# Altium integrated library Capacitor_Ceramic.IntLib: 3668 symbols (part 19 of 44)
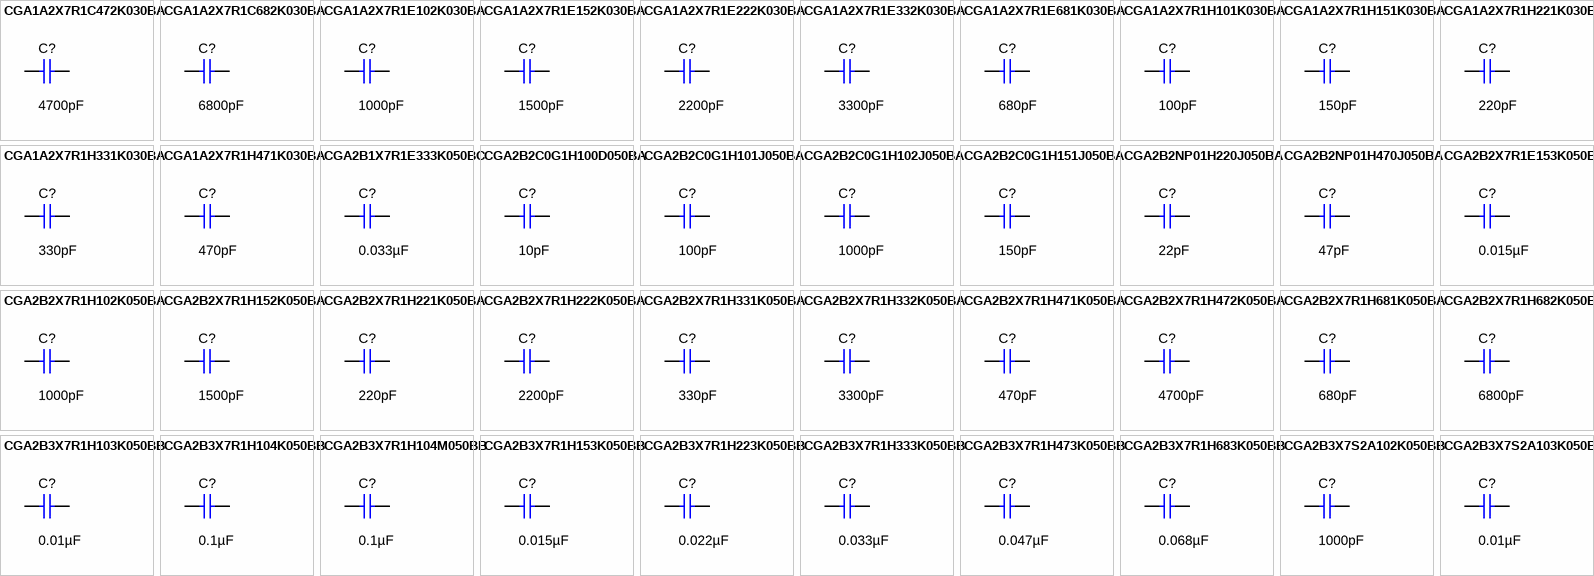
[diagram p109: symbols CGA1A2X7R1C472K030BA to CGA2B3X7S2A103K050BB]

## CGA2B2C0G1H101J050BA
designator C?  ValueDisplayed: 100pF  (hidden comment: CGA2B2C0G1H101J050BA)
CAP, CERM, 100 pF, 50 V,+/- 5%, C0G/NP0, AEC-Q200 Grade 1, 0402; Manufacturer: TDK; Polarized: N; CompType: Capacitor; Value: 100pF; U/M: EA; Cap_F: 0.0000000001; Tolerance_%: 5; VDC_V: 50; Value2: 50V; TaMin_C: -55; TaMax_C: 125; Cap_Case: 0402; SizeArea_mm2: 0.5; SizeAreaWB_mm2: 3; SizeX_mm: 1; SizeZ_mm: 0.6; AEC Category: Q200; AEC Qualified: Y; Green_Lifecycle: Active; Green_REACh: Passed
signal-integrity model Cap
simulation model Cap
footprint 0402
footprint 0402M
footprint 0402L
footprint 0402S
pins: 1, 2

## CGA2B2C0G1H102J050BA
designator C?  ValueDisplayed: 1000pF  (hidden comment: CGA2B2C0G1H102J050BA)
CAP, CERM, 1000 pF, 50 V,+/- 5%, C0G/NP0, AEC-Q200 Grade 1, 0402; Manufacturer: TDK; Polarized: N; CompType: Capacitor; Value: 1000pF; U/M: EA; Cap_F: 0.000000001; Tolerance_%: 5; VDC_V: 50; Value2: 50V; TaMin_C: -55; TaMax_C: 125; Cap_Case: 0402; SizeArea_mm2: 0.5; SizeAreaWB_mm2: 3; SizeX_mm: 1; SizeZ_mm: 0.6; AEC Category: Q200; AEC Qualified: Y; Green_Lifecycle: Active; Green_REACh: Passed
signal-integrity model Cap
simulation model Cap
footprint 0402
footprint 0402M
footprint 0402L
footprint 0402S
pins: 1, 2

## CGA2B2C0G1H151J050BA
designator C?  ValueDisplayed: 150pF  (hidden comment: CGA2B2C0G1H151J050BA)
CAP, CERM, 150 pF, 50 V,+/- 5%, C0G/NP0, AEC-Q200 Grade 1, 0402; Manufacturer: TDK; Polarized: N; CompType: Capacitor; Value: 150pF; U/M: EA; Cap_F: 0.00000000015; Tolerance_%: 5; VDC_V: 50; Value2: 50V; TaMin_C: -55; TaMax_C: 125; Cap_Case: 0402; SizeArea_mm2: 0.5; SizeAreaWB_mm2: 3; SizeX_mm: 1; SizeZ_mm: 0.6; AEC Category: Q200; AEC Qualified: Y
signal-integrity model Cap
simulation model Cap
footprint 0402
footprint 0402M
footprint 0402L
footprint 0402S
pins: 1, 2

## CGA2B2NP01H220J050BA
designator C?  ValueDisplayed: 22pF  (hidden comment: CGA2B2NP01H220J050BA)
CAP, CERM, 22 pF, 50 V,+/- 5%, C0G/NP0, AEC-Q200 Grade 1, 0402; Manufacturer: TDK; Polarized: N; CompType: Capacitor; Value: 22pF; U/M: EA; Cap_F: 0.000000000022; Tolerance_%: 5; VDC_V: 50; Value2: 50V; TaMin_C: -55; TaMax_C: 125; Cap_Case: 0402; SizeArea_mm2: 0.5; SizeAreaWB_mm2: 3; SizeX_mm: 1; SizeZ_mm: 0.6; AEC Category: Q200; AEC Qualified: Y
signal-integrity model Cap
simulation model Cap
footprint 0402
footprint 0402M
footprint 0402L
footprint 0402S
pins: 1, 2

## CGA2B2NP01H470J050BA
designator C?  ValueDisplayed: 47pF  (hidden comment: CGA2B2NP01H470J050BA)
CAP, CERM, 47 pF, 50 V,+/- 5%, C0G/NP0, AEC-Q200 Grade 0, 0402; Manufacturer: TDK; Polarized: N; CompType: Capacitor; Value: 47pF; U/M: EA; Cap_F: 0.000000000047; Tolerance_%: 5; VDC_V: 50; Value2: 50V; TaMin_C: -55; TaMax_C: 150; Cap_Case: 0402; SizeArea_mm2: 0.5; SizeAreaWB_mm2: 3; SizeX_mm: 1; SizeZ_mm: 0.6; AEC Category: Q200; AEC Qualified: Y; AEC Grade: 0
signal-integrity model Cap
simulation model Cap
footprint 0402
footprint 0402M
footprint 0402L
footprint 0402S
pins: 1, 2

## CGA2B2X7R1E153K050BA
designator C?  ValueDisplayed: 0.015µF  (hidden comment: CGA2B2X7R1E153K050BA)
CAP, CERM, 0.015 µF, 25 V,+/- 10%, X7R, AEC-Q200 Grade 1, 0402; Manufacturer: TDK; Polarized: N; CompType: Capacitor; Value: 0.015uF; U/M: EA; Cap_F: 0.000000015; Tolerance_%: 10; VDC_V: 25; Value2: 25V; TaMin_C: -55; TaMax_C: 125; Cap_Case: 0402; SizeArea_mm2: 0.5; SizeAreaWB_mm2: 3; SizeX_mm: 1; SizeZ_mm: 0.6; AEC Category: Q200; AEC Qualified: Y
signal-integrity model Cap
simulation model Cap
footprint 0402
footprint 0402M
footprint 0402L
footprint 0402S
pins: 1, 2

## CGA2B2X7R1H102K050BA
designator C?  ValueDisplayed: 1000pF  (hidden comment: CGA2B2X7R1H102K050BA)
CAP, CERM, 1000 pF, 50 V,+/- 10%, X7R, AEC-Q200 Grade 1, 0402; Manufacturer: TDK; Polarized: N; CompType: Capacitor; Value: 1000pF; U/M: EA; Cap_F: 0.000000001; Tolerance_%: 10; ESR_ohm: 2.25564; Value1: 2.25564 ohm; VDC_V: 50; Value2: 50V; IRMS_A: 0.280466; TaMin_C: -55; TaMax_C: 125; Cap_Case: 0402; SizeArea_mm2: 0.5; SizeAreaWB_mm2: 3; SizeX_mm: 1; SizeZ_mm: 0.6; AEC Category: Q200; AEC Qualified: Y
signal-integrity model Cap
simulation model Cap
footprint 0402
footprint 0402M
footprint 0402L
footprint 0402S
pins: 1, 2

## CGA2B2X7R1H152K050BA
designator C?  ValueDisplayed: 1500pF  (hidden comment: CGA2B2X7R1H152K050BA)
CAP, CERM, 1500 pF, 50 V,+/- 10%, X7R, AEC-Q200 Grade 1, 0402; Manufacturer: TDK; Polarized: N; CompType: Capacitor; Value: 1500pF; U/M: EA; Cap_F: 0.0000000015; Tolerance_%: 10; ESR_ohm: 1.65812; Value1: 1.65812 ohm; VDC_V: 50; Value2: 50V; IRMS_A: 0.254831; TaMin_C: -55; TaMax_C: 125; Cap_Case: 0402; SizeArea_mm2: 0.5; SizeAreaWB_mm2: 3; SizeX_mm: 1; SizeZ_mm: 0.6; AEC Category: Q200; AEC Qualified: Y
signal-integrity model Cap
simulation model Cap
footprint 0402
footprint 0402M
footprint 0402L
footprint 0402S
pins: 1, 2

## CGA2B2X7R1H221K050BA
designator C?  ValueDisplayed: 220pF  (hidden comment: CGA2B2X7R1H221K050BA)
CAP, CERM, 220 pF, 50 V,+/- 10%, X7R, AEC-Q200 Grade 1, 0402; Manufacturer: TDK; Polarized: N; CompType: Capacitor; Value: 220pF; U/M: EA; Cap_F: 0.00000000022; Tolerance_%: 10; ESR_ohm: 9.829; Value1: 9.829 ohm; VDC_V: 50; Value2: 50V; IRMS_A: 0.201345; TaMin_C: -55; TaMax_C: 125; Cap_Case: 0402; SizeArea_mm2: 0.5; SizeAreaWB_mm2: 3; SizeX_mm: 1; SizeZ_mm: 0.6; AEC Category: Q200; AEC Qualified: Y
signal-integrity model Cap
simulation model Cap
footprint 0402
footprint 0402M
footprint 0402L
footprint 0402S
pins: 1, 2

## CGA2B2X7R1H222K050BA
designator C?  ValueDisplayed: 2200pF  (hidden comment: CGA2B2X7R1H222K050BA)
CAP, CERM, 2200 pF, 50 V,+/- 10%, X7R, AEC-Q200 Grade 1, 0402; Manufacturer: TDK; Polarized: N; CompType: Capacitor; Value: 2200pF; U/M: EA; Cap_F: 0.0000000022; Tolerance_%: 10; ESR_ohm: 1.07794; Value1: 1.07794 ohm; VDC_V: 50; Value2: 50V; IRMS_A: 0.264071; TaMin_C: -55; TaMax_C: 125; Cap_Case: 0402; SizeArea_mm2: 0.5; SizeAreaWB_mm2: 3; SizeX_mm: 1; SizeZ_mm: 0.6; AEC Category: Q200; AEC Qualified: Y
signal-integrity model Cap
simulation model Cap
footprint 0402
footprint 0402M
footprint 0402L
footprint 0402S
pins: 1, 2

## CGA2B2X7R1H331K050BA
designator C?  ValueDisplayed: 330pF  (hidden comment: CGA2B2X7R1H331K050BA)
CAP, CERM, 330 pF, 50 V,+/- 10%, X7R, AEC-Q200 Grade 1, 0402; Manufacturer: TDK; Polarized: N; CompType: Capacitor; Value: 330pF; U/M: EA; Cap_F: 0.00000000033; Tolerance_%: 10; ESR_ohm: 6.53276; Value1: 6.53276 ohm; VDC_V: 50; Value2: 50V; IRMS_A: 0.212649; TaMin_C: -55; TaMax_C: 125; Cap_Case: 0402; SizeArea_mm2: 0.5; SizeAreaWB_mm2: 3; SizeX_mm: 1; SizeZ_mm: 0.6; AEC Category: Q200; AEC Qualified: Y
signal-integrity model Cap
simulation model Cap
footprint 0402
footprint 0402M
footprint 0402L
footprint 0402S
pins: 1, 2

## CGA2B2X7R1H332K050BA
designator C?  ValueDisplayed: 3300pF  (hidden comment: CGA2B2X7R1H332K050BA)
CAP, CERM, 3300 pF, 50 V,+/- 10%, X7R, AEC-Q200 Grade 1, 0402; Manufacturer: TDK; Polarized: N; CompType: Capacitor; Value: 3300pF; U/M: EA; Cap_F: 0.0000000033; Tolerance_%: 10; ESR_ohm: 0.785178; Value1: 0.785178 ohm; VDC_V: 50; Value2: 50V; IRMS_A: 0.272902; TaMin_C: -55; TaMax_C: 125; Cap_Case: 0402; SizeArea_mm2: 0.5; SizeAreaWB_mm2: 3; SizeX_mm: 1; SizeZ_mm: 0.6; AEC Category: Q200; AEC Qualified: Y; Green_Lifecycle: Active; Green_REACh: Passed
signal-integrity model Cap
simulation model Cap
footprint 0402
footprint 0402M
footprint 0402L
footprint 0402S
pins: 1, 2

## CGA2B2X7R1H471K050BA
designator C?  ValueDisplayed: 470pF  (hidden comment: CGA2B2X7R1H471K050BA)
CAP, CERM, 470 pF, 50 V,+/- 10%, X7R, AEC-Q200 Grade 1, 0402; Manufacturer: TDK; Polarized: N; CompType: Capacitor; Value: 470pF; U/M: EA; Cap_F: 0.00000000047; Tolerance_%: 10; ESR_ohm: 4.96489; Value1: 4.96489 ohm; VDC_V: 50; Value2: 50V; IRMS_A: 0.228414; TaMin_C: -55; TaMax_C: 125; Cap_Case: 0402; SizeArea_mm2: 0.5; SizeAreaWB_mm2: 3; SizeX_mm: 1; SizeZ_mm: 0.6; AEC Category: Q200; AEC Qualified: Y
signal-integrity model Cap
simulation model Cap
footprint 0402
footprint 0402M
footprint 0402L
footprint 0402S
pins: 1, 2

## CGA2B2X7R1H472K050BA
designator C?  ValueDisplayed: 4700pF  (hidden comment: CGA2B2X7R1H472K050BA)
CAP, CERM, 4700 pF, 50 V,+/- 10%, X7R, AEC-Q200 Grade 1, 0402; Manufacturer: TDK; Polarized: N; CompType: Capacitor; Value: 4700pF; U/M: EA; Cap_F: 0.0000000047; Tolerance_%: 10; ESR_ohm: 0.413508; Value1: 0.413508 ohm; VDC_V: 50; Value2: 50V; IRMS_A: 0.330878; TaMin_C: -55; TaMax_C: 125; Cap_Case: 0402; SizeArea_mm2: 0.5; SizeAreaWB_mm2: 3; SizeX_mm: 1; SizeZ_mm: 0.6; AEC Category: Q200; AEC Qualified: Y
signal-integrity model Cap
simulation model Cap
footprint 0402
footprint 0402M
footprint 0402L
footprint 0402S
pins: 1, 2

## CGA2B2X7R1H681K050BA
designator C?  ValueDisplayed: 680pF  (hidden comment: CGA2B2X7R1H681K050BA)
CAP, CERM, 680 pF, 50 V,+/- 10%, X7R, AEC-Q200 Grade 1, 0402; Manufacturer: TDK; Polarized: N; CompType: Capacitor; Value: 680pF; U/M: EA; Cap_F: 0.00000000068; Tolerance_%: 10; ESR_ohm: 3.07785; Value1: 3.07785 ohm; VDC_V: 50; Value2: 50V; IRMS_A: 0.25763; TaMin_C: -55; TaMax_C: 125; Cap_Case: 0402; SizeArea_mm2: 0.5; SizeAreaWB_mm2: 3; SizeX_mm: 1; SizeZ_mm: 0.6; AEC Category: Q200; AEC Qualified: Y
signal-integrity model Cap
simulation model Cap
footprint 0402
footprint 0402M
footprint 0402L
footprint 0402S
pins: 1, 2

## CGA2B2X7R1H682K050BA
designator C?  ValueDisplayed: 6800pF  (hidden comment: CGA2B2X7R1H682K050BA)
CAP, CERM, 6800 pF, 50 V,+/- 10%, X7R, AEC-Q200 Grade 1, 0402; Manufacturer: TDK; Polarized: N; CompType: Capacitor; Value: 6800pF; U/M: EA; Cap_F: 0.0000000068; Tolerance_%: 10; ESR_ohm: 0.391597; Value1: 0.391597 ohm; VDC_V: 50; Value2: 50V; IRMS_A: 0.315526; TaMin_C: -55; TaMax_C: 125; Cap_Case: 0402; SizeArea_mm2: 0.5; SizeAreaWB_mm2: 3; SizeX_mm: 1; SizeZ_mm: 0.6; AEC Category: Q200; AEC Qualified: Y
signal-integrity model Cap
simulation model Cap
footprint 0402
footprint 0402M
footprint 0402L
footprint 0402S
pins: 1, 2

## CGA2B3X7R1H103K050BB
designator C?  ValueDisplayed: 0.01µF  (hidden comment: CGA2B3X7R1H103K050BB)
CAP, CERM, 0.01 µF, 50 V,+/- 10%, X7R, AEC-Q200 Grade 1, 0402; Manufacturer: TDK; Polarized: N; CompType: Capacitor; Value: 0.01uF; U/M: EA; Cap_F: 0.00000001; Tolerance_%: 10; ESR_ohm: 0.333065; Value1: 0.333065 ohm; VDC_V: 50; Value2: 50V; IRMS_A: 0.323373; TaMin_C: -55; TaMax_C: 125; Cap_Case: 0402; SizeArea_mm2: 0.5; SizeAreaWB_mm2: 3; SizeX_mm: 1; SizeZ_mm: 0.6; AEC Category: Q200; AEC Qualified: Y; Green_Lifecycle: Active; Green_REACh: Passed
signal-integrity model Cap
simulation model Cap
footprint 0402
footprint 0402M
footprint 0402L
footprint 0402S
pins: 1, 2

## CGA2B3X7R1H104K050BB
designator C?  ValueDisplayed: 0.1µF  (hidden comment: CGA2B3X7R1H104K050BB)
CAP, CERM, 0.1 µF, 50 V,+/- 10%, X7R, AEC-Q200 Grade 1, 0402; Manufacturer: TDK; Polarized: N; CompType: Capacitor; Value: 0.1uF; U/M: EA; Cap_F: 0.0000001; Tolerance_%: 10; ESR_ohm: 0.039064; Value1: 0.039064 ohm; VDC_V: 50; Value2: 50V; IRMS_A: 0.814669; TaMin_C: -55; TaMax_C: 125; Cap_Case: 0402; SizeArea_mm2: 0.5; SizeAreaWB_mm2: 3; SizeX_mm: 1; SizeZ_mm: 0.6; AEC Category: Q200; AEC Qualified: Y; Green_Lifecycle: Active; Green_REACh: Passed
signal-integrity model Cap
simulation model Cap
footprint 0402
footprint 0402M
footprint 0402L
footprint 0402S
pins: 1, 2

## CGA2B3X7R1H104M050BB
designator C?  ValueDisplayed: 0.1µF  (hidden comment: CGA2B3X7R1H104M050BB)
CAP, CERM, 0.1 µF, 50 V,+/- 20%, X7R, AEC-Q200 Grade 1, 0402; Manufacturer: TDK; Polarized: N; CompType: Capacitor; Value: 0.1uF; U/M: EA; Cap_F: 0.0000001; Tolerance_%: 20; VDC_V: 50; Value2: 50V; TaMin_C: -55; TaMax_C: 125; Cap_Case: 0402; SizeArea_mm2: 0.5; SizeAreaWB_mm2: 3; SizeX_mm: 1; SizeZ_mm: 0.6; AEC Category: Q200; AEC Qualified: Y
signal-integrity model Cap
simulation model Cap
footprint 0402
footprint 0402M
footprint 0402L
footprint 0402S
pins: 1, 2

## CGA2B3X7R1H153K050BB
designator C?  ValueDisplayed: 0.015µF  (hidden comment: CGA2B3X7R1H153K050BB)
CAP, CERM, 0.015 µF, 50 V,+/- 10%, X7R, AEC-Q200 Grade 1, 0402; Manufacturer: TDK; Polarized: N; CompType: Capacitor; Value: 0.015uF; U/M: EA; Cap_F: 0.000000015; Tolerance_%: 10; ESR_ohm: 0.2162; Value1: 0.2162 ohm; VDC_V: 50; Value2: 50V; IRMS_A: 0.379389; TaMin_C: -55; TaMax_C: 125; Cap_Case: 0402; SizeArea_mm2: 0.5; SizeAreaWB_mm2: 3; SizeX_mm: 1; SizeZ_mm: 0.6; AEC Category: Q200; AEC Qualified: Y
signal-integrity model Cap
simulation model Cap
footprint 0402
footprint 0402M
footprint 0402L
footprint 0402S
pins: 1, 2

## CGA2B3X7R1H223K050BB
designator C?  ValueDisplayed: 0.022µF  (hidden comment: CGA2B3X7R1H223K050BB)
CAP, CERM, 0.022 µF, 50 V,+/- 10%, X7R, AEC-Q200 Grade 1, 0402; Manufacturer: TDK; Polarized: N; CompType: Capacitor; Value: 0.022uF; U/M: EA; Cap_F: 0.000000022; Tolerance_%: 10; ESR_ohm: 0.141987; Value1: 0.141987 ohm; VDC_V: 50; Value2: 50V; IRMS_A: 0.451393; TaMin_C: -55; TaMax_C: 125; Cap_Case: 0402; SizeArea_mm2: 0.5; SizeAreaWB_mm2: 3; SizeX_mm: 1; SizeZ_mm: 0.6; AEC Category: Q200; AEC Qualified: Y
signal-integrity model Cap
simulation model Cap
footprint 0402
footprint 0402M
footprint 0402L
footprint 0402S
pins: 1, 2

## CGA2B3X7R1H333K050BB
designator C?  ValueDisplayed: 0.033µF  (hidden comment: CGA2B3X7R1H333K050BB)
CAP, CERM, 0.033 µF, 50 V,+/- 10%, X7R, AEC-Q200 Grade 1, 0402; Manufacturer: TDK; Polarized: N; CompType: Capacitor; Value: 0.033uF; U/M: EA; Cap_F: 0.000000033; Tolerance_%: 10; ESR_ohm: 0.098477; Value1: 0.098477 ohm; VDC_V: 50; Value2: 50V; IRMS_A: 0.53078; TaMin_C: -55; TaMax_C: 125; Cap_Case: 0402; SizeArea_mm2: 0.5; SizeAreaWB_mm2: 3; SizeX_mm: 1; SizeZ_mm: 0.6; AEC Category: Q200; AEC Qualified: Y
signal-integrity model Cap
simulation model Cap
footprint 0402
footprint 0402M
footprint 0402L
footprint 0402S
pins: 1, 2

## CGA2B3X7R1H473K050BB
designator C?  ValueDisplayed: 0.047µF  (hidden comment: CGA2B3X7R1H473K050BB)
CAP, CERM, 0.047 µF, 50 V,+/- 10%, X7R, AEC-Q200 Grade 1, 0402; Manufacturer: TDK; Polarized: N; CompType: Capacitor; Value: 0.047uF; U/M: EA; Cap_F: 0.000000047; Tolerance_%: 10; ESR_ohm: 0.06407; Value1: 0.06407 ohm; VDC_V: 50; Value2: 50V; IRMS_A: 0.646122; TaMin_C: -55; TaMax_C: 125; Cap_Case: 0402; SizeArea_mm2: 0.5; SizeAreaWB_mm2: 3; SizeX_mm: 1; SizeZ_mm: 0.6; AEC Category: Q200; AEC Qualified: Y
signal-integrity model Cap
simulation model Cap
footprint 0402
footprint 0402M
footprint 0402L
footprint 0402S
pins: 1, 2

## CGA2B3X7R1H683K050BB
designator C?  ValueDisplayed: 0.068µF  (hidden comment: CGA2B3X7R1H683K050BB)
CAP, CERM, 0.068 µF, 50 V,+/- 10%, X7R, AEC-Q200 Grade 1, 0402; Manufacturer: TDK; Polarized: N; CompType: Capacitor; Value: 0.068uF; U/M: EA; Cap_F: 0.000000068; Tolerance_%: 10; ESR_ohm: 0.05606; Value1: 0.05606 ohm; VDC_V: 50; Value2: 50V; IRMS_A: 0.684724; TaMin_C: -55; TaMax_C: 125; Cap_Case: 0402; SizeArea_mm2: 0.5; SizeAreaWB_mm2: 3; SizeX_mm: 1; SizeZ_mm: 0.6; AEC Category: Q200; AEC Qualified: Y
signal-integrity model Cap
simulation model Cap
footprint 0402
footprint 0402M
footprint 0402L
footprint 0402S
pins: 1, 2

## CGA2B3X7S2A102K050BB
designator C?  ValueDisplayed: 1000pF  (hidden comment: CGA2B3X7S2A102K050BB)
CAP, CERM, 1000 pF, 100 V,+/- 10%, X7S, AEC-Q200 Grade 1, 0402; Manufacturer: TDK; Polarized: N; CompType: Capacitor; Value: 1000pF; U/M: EA; Cap_F: 0.000000001; Tolerance_%: 10; ESR_ohm: 2.71151; Value1: 2.71151 ohm; VDC_V: 100; Value2: 100V; IRMS_A: 0.264589; TaMin_C: -55; TaMax_C: 125; Cap_Case: 0402; SizeArea_mm2: 0.5; SizeAreaWB_mm2: 3; SizeX_mm: 1; SizeZ_mm: 0.6; AEC Category: Q200; AEC Qualified: Y
signal-integrity model Cap
simulation model Cap
footprint 0402
footprint 0402M
footprint 0402L
footprint 0402S
pins: 1, 2

## CGA2B3X7S2A103K050BB
designator C?  ValueDisplayed: 0.01µF  (hidden comment: CGA2B3X7S2A103K050BB)
CAP, CERM, 0.01 µF, 100 V,+/- 10%, X7S, AEC-Q200 Grade 1, 0402; Manufacturer: TDK; Polarized: N; CompType: Capacitor; Value: 0.01uF; U/M: EA; Cap_F: 0.00000001; Tolerance_%: 10; ESR_ohm: 0.410191; Value1: 0.410191 ohm; VDC_V: 100; Value2: 100V; IRMS_A: 0.291729; TaMin_C: -55; TaMax_C: 125; Cap_Case: 0402; SizeArea_mm2: 0.5; SizeAreaWB_mm2: 3; SizeX_mm: 1; SizeZ_mm: 0.6; AEC Category: Q200; AEC Qualified: Y
signal-integrity model Cap
simulation model Cap
footprint 0402
footprint 0402M
footprint 0402L
footprint 0402S
pins: 1, 2

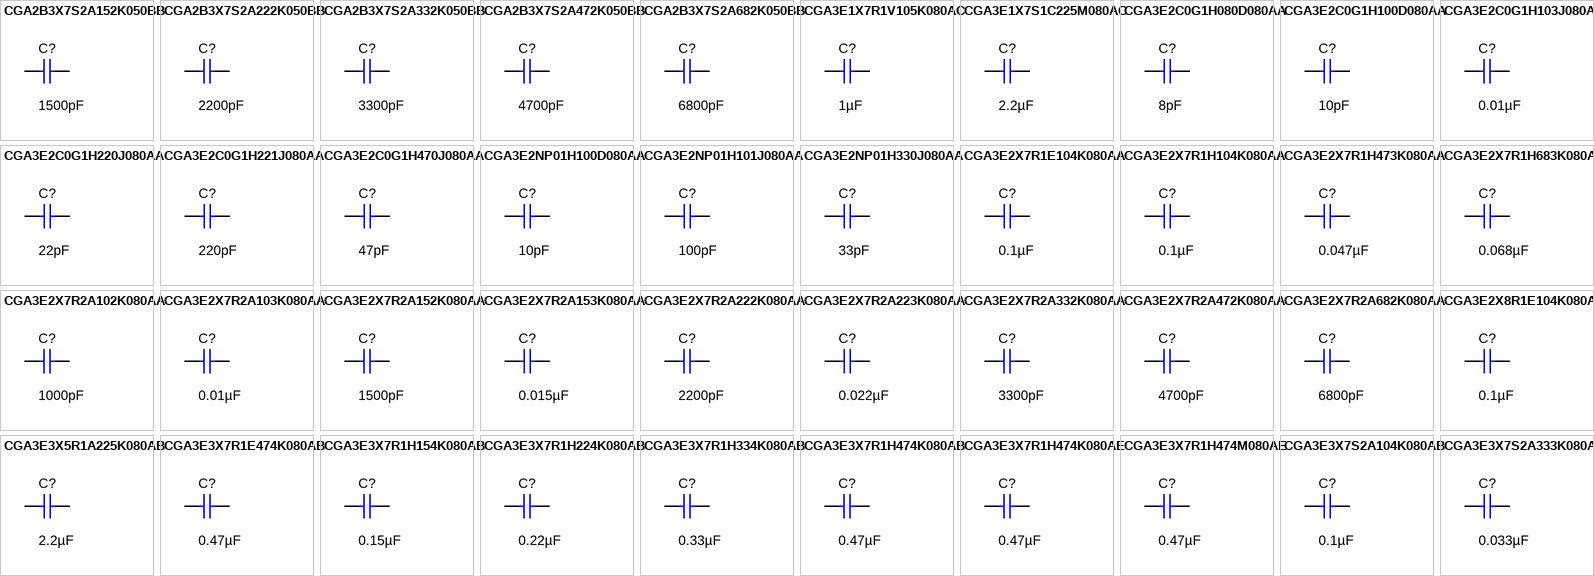
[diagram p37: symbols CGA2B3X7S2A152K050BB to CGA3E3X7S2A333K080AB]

## CGA2B3X7S2A152K050BB
designator C?  ValueDisplayed: 1500pF  (hidden comment: CGA2B3X7S2A152K050BB)
CAP, CERM, 1500 pF, 100 V,+/- 10%, X7S, AEC-Q200 Grade 1, 0402; Manufacturer: TDK; Polarized: N; CompType: Capacitor; Value: 1500pF; U/M: EA; Cap_F: 0.0000000015; Tolerance_%: 10; ESR_ohm: 1.89793; Value1: 1.89793 ohm; VDC_V: 100; Value2: 100V; IRMS_A: 0.24508; TaMin_C: -55; TaMax_C: 125; Cap_Case: 0402; SizeArea_mm2: 0.5; SizeAreaWB_mm2: 3; SizeX_mm: 1; SizeZ_mm: 0.6; AEC Category: Q200; AEC Qualified: Y
signal-integrity model Cap
simulation model Cap
footprint 0402
footprint 0402M
footprint 0402L
footprint 0402S
pins: 1, 2

## CGA2B3X7S2A222K050BB
designator C?  ValueDisplayed: 2200pF  (hidden comment: CGA2B3X7S2A222K050BB)
CAP, CERM, 2200 pF, 100 V,+/- 10%, X7S, AEC-Q200 Grade 1, 0402; Manufacturer: TDK; Polarized: N; CompType: Capacitor; Value: 2200pF; U/M: EA; Cap_F: 0.0000000022; Tolerance_%: 10; ESR_ohm: 1.26014; Value1: 1.26014 ohm; VDC_V: 100; Value2: 100V; IRMS_A: 0.248698; TaMin_C: -55; TaMax_C: 125; Cap_Case: 0402; SizeArea_mm2: 0.5; SizeAreaWB_mm2: 3; SizeX_mm: 1; SizeZ_mm: 0.6; AEC Category: Q200; AEC Qualified: Y
signal-integrity model Cap
simulation model Cap
footprint 0402
footprint 0402M
footprint 0402L
footprint 0402S
pins: 1, 2

## CGA2B3X7S2A332K050BB
designator C?  ValueDisplayed: 3300pF  (hidden comment: CGA2B3X7S2A332K050BB)
CAP, CERM, 3300 pF, 100 V,+/- 10%, X7S, AEC-Q200 Grade 1, 0402; Manufacturer: TDK; Polarized: N; CompType: Capacitor; Value: 3300pF; U/M: EA; Cap_F: 0.0000000033; Tolerance_%: 10; ESR_ohm: 0.945559; Value1: 0.945559 ohm; VDC_V: 100; Value2: 100V; IRMS_A: 0.245346; TaMin_C: -55; TaMax_C: 125; Cap_Case: 0402; SizeArea_mm2: 0.5; SizeAreaWB_mm2: 3; SizeX_mm: 1; SizeZ_mm: 0.6; AEC Category: Q200; AEC Qualified: Y
signal-integrity model Cap
simulation model Cap
footprint 0402
footprint 0402M
footprint 0402L
footprint 0402S
pins: 1, 2

## CGA2B3X7S2A472K050BB
designator C?  ValueDisplayed: 4700pF  (hidden comment: CGA2B3X7S2A472K050BB)
CAP, CERM, 4700 pF, 100 V,+/- 10%, X7S, AEC-Q200 Grade 1, 0402; Manufacturer: TDK; Polarized: N; CompType: Capacitor; Value: 4700pF; U/M: EA; Cap_F: 0.0000000047; Tolerance_%: 10; ESR_ohm: 0.685549; Value1: 0.685549 ohm; VDC_V: 100; Value2: 100V; IRMS_A: 0.263706; TaMin_C: -55; TaMax_C: 125; Cap_Case: 0402; SizeArea_mm2: 0.5; SizeAreaWB_mm2: 3; SizeX_mm: 1; SizeZ_mm: 0.6; AEC Category: Q200; AEC Qualified: Y
signal-integrity model Cap
simulation model Cap
footprint 0402
footprint 0402M
footprint 0402L
footprint 0402S
pins: 1, 2

## CGA2B3X7S2A682K050BB
designator C?  ValueDisplayed: 6800pF  (hidden comment: CGA2B3X7S2A682K050BB)
CAP, CERM, 6800 pF, 100 V,+/- 10%, X7S, AEC-Q200 Grade 1, 0402; Manufacturer: TDK; Polarized: N; CompType: Capacitor; Value: 6800pF; U/M: EA; Cap_F: 0.0000000068; Tolerance_%: 10; ESR_ohm: 0.523223; Value1: 0.523223 ohm; VDC_V: 100; Value2: 100V; IRMS_A: 0.273561; TaMin_C: -55; TaMax_C: 125; Cap_Case: 0402; SizeArea_mm2: 0.5; SizeAreaWB_mm2: 3; SizeX_mm: 1; SizeZ_mm: 0.6; AEC Category: Q200; AEC Qualified: Y
signal-integrity model Cap
simulation model Cap
footprint 0402
footprint 0402M
footprint 0402L
footprint 0402S
pins: 1, 2

## CGA3E1X7R1V105K080AC
designator C?  ValueDisplayed: 1µF  (hidden comment: CGA3E1X7R1V105K080AC)
CAP, CERM, 1 µF, 35 V,+/- 10%, X7R, AEC-Q200 Grade 1, 0603; Manufacturer: TDK; Polarized: N; CompType: Capacitor; Value: 1uF; U/M: EA; Cap_F: 0.000001; Tolerance_%: 10; ESR_ohm: 0.005522; Value1: 0.005522 ohm; VDC_V: 35; Value2: 35V; IRMS_A: 2.21617; TaMin_C: -55; TaMax_C: 125; Cap_Case: 0603; SizeArea_mm2: 1.28; SizeAreaWB_mm2: 4.68; SizeX_mm: 1.6; SizeY_mm: 0.8; SizeZ_mm: 1; AEC Category: Q200; AEC Qualified: Y
signal-integrity model Cap
simulation model Cap
footprint 0603
footprint 0603M
footprint 0603L
footprint 0603_HV
footprint 0603S
pins: 1, 2

## CGA3E1X7S1C225M080AC
designator C?  ValueDisplayed: 2.2µF  (hidden comment: CGA3E1X7S1C225M080AC)
CAP, CERM, 2.2 µF, 16 V,+/- 20%, X7S, AEC-Q200 Grade 1, 0603; Manufacturer: TDK; Polarized: N; CompType: Capacitor; Value: 2.2uF; U/M: EA; Cap_F: 0.0000022; Tolerance_%: 20; VDC_V: 16; Value2: 16V; TaMin_C: -55; TaMax_C: 125; Cap_Case: 0603; SizeArea_mm2: 1.28; SizeAreaWB_mm2: 4.68; SizeX_mm: 1.6; SizeY_mm: 0.8; SizeZ_mm: 1; AEC Category: Q200; AEC Qualified: Y
signal-integrity model Cap
simulation model Cap
footprint 0603
footprint 0603M
footprint 0603L
footprint 0603_HV
footprint 0603S
pins: 1, 2

## CGA3E2C0G1H080D080AA
designator C?  ValueDisplayed: 8pF  (hidden comment: CGA3E2C0G1H080D080AA)
CAP, CERM, 8 pF, 50 V,+/- 6.25%, C0G/NP0, AEC-Q200 Grade 1, 0603; Manufacturer: TDK; Polarized: N; CompType: Capacitor; Value: 8pF; U/M: EA; Cap_F: 0.000000000008; Tolerance_%: 6.25; VDC_V: 50; Value2: 50V; TaMin_C: -55; TaMax_C: 125; Cap_Case: 0603; SizeArea_mm2: 1.28; SizeAreaWB_mm2: 4.68; SizeX_mm: 1.6; SizeY_mm: 0.8; SizeZ_mm: 1; AEC Category: Q200; AEC Qualified: Y
signal-integrity model Cap
simulation model Cap
footprint 0603
footprint 0603M
footprint 0603L
footprint 0603_HV
footprint 0603S
pins: 1, 2

## CGA3E2C0G1H100D080AA
designator C?  ValueDisplayed: 10pF  (hidden comment: CGA3E2C0G1H100D080AA)
CAP, CERM, 10 pF, 50 V,+/- 5%, C0G/NP0, AEC-Q200 Grade 1, 0603; Manufacturer: TDK; Polarized: N; CompType: Capacitor; Value: 10pF; U/M: EA; Cap_F: 0.00000000001; Tolerance_%: 5; VDC_V: 50; Value2: 50V; TaMin_C: -55; TaMax_C: 125; Cap_Case: 0603; SizeArea_mm2: 1.28; SizeAreaWB_mm2: 4.68; SizeX_mm: 1.6; SizeY_mm: 0.8; SizeZ_mm: 1; AEC Category: Q200; AEC Qualified: Y
signal-integrity model Cap
simulation model Cap
footprint 0603
footprint 0603M
footprint 0603L
footprint 0603_HV
footprint 0603S
pins: 1, 2

## CGA3E2C0G1H103J080AA
designator C?  ValueDisplayed: 0.01µF  (hidden comment: CGA3E2C0G1H103J080AA)
CAP, CERM, 0.01 µF, 50 V,+/- 5%, C0G/NP0, AEC-Q200 Grade 1, 0603; Manufacturer: TDK; Polarized: N; CompType: Capacitor; Value: 0.01uF; U/M: EA; Cap_F: 0.00000001; Tolerance_%: 5; VDC_V: 50; Value2: 50V; TaMin_C: -55; TaMax_C: 125; Cap_Case: 0603; SizeArea_mm2: 1.28; SizeAreaWB_mm2: 4.68; SizeX_mm: 1.6; SizeY_mm: 0.8; SizeZ_mm: 1; AEC Category: Q200; AEC Qualified: Y; Green_Lifecycle: Active; Green_REACh: Passed
signal-integrity model Cap
simulation model Cap
footprint 0603
footprint 0603M
footprint 0603L
footprint 0603_HV
footprint 0603S
pins: 1, 2

## CGA3E2C0G1H220J080AA
designator C?  ValueDisplayed: 22pF  (hidden comment: CGA3E2C0G1H220J080AA)
CAP, CERM, 22 pF, 50 V,+/- 5%, C0G/NP0, AEC-Q200 Grade 1, 0603; Manufacturer: TDK; Polarized: N; CompType: Capacitor; Value: 22pF; U/M: EA; Cap_F: 0.000000000022; Tolerance_%: 5; VDC_V: 50; Value2: 50V; TaMin_C: -55; TaMax_C: 125; Cap_Case: 0603; SizeArea_mm2: 1.28; SizeAreaWB_mm2: 4.68; SizeX_mm: 1.6; SizeY_mm: 0.8; SizeZ_mm: 1; AEC Category: Q200; AEC Qualified: Y
signal-integrity model Cap
simulation model Cap
footprint 0603
footprint 0603M
footprint 0603L
footprint 0603_HV
footprint 0603S
pins: 1, 2

## CGA3E2C0G1H221J080AA
designator C?  ValueDisplayed: 220pF  (hidden comment: CGA3E2C0G1H221J080AA)
CAP, CERM, 220 pF, 20 V,+/- 5%, C0G/NP0, AEC-Q200 Grade 1, 0603; Manufacturer: TDK; Polarized: N; CompType: Capacitor; Value: 220pF; U/M: EA; Cap_F: 0.00000000022; Tolerance_%: 5; VDC_V: 20; Value2: 20V; TaMin_C: -55; TaMax_C: 125; Cap_Case: 0603; SizeArea_mm2: 1.28; SizeAreaWB_mm2: 4.68; SizeX_mm: 1.6; SizeY_mm: 0.8; SizeZ_mm: 1; AEC Category: Q200; AEC Qualified: Y
signal-integrity model Cap
simulation model Cap
footprint 0603
footprint 0603M
footprint 0603L
footprint 0603_HV
footprint 0603S
pins: 1, 2

## CGA3E2C0G1H470J080AA
designator C?  ValueDisplayed: 47pF  (hidden comment: CGA3E2C0G1H470J080AA)
CAP, CERM, 47 pF, 50 V,+/- 5%, C0G/NP0, AEC-Q200 Grade 1, 0603; Manufacturer: TDK; Polarized: N; CompType: Capacitor; Value: 47pF; U/M: EA; Cap_F: 0.000000000047; Tolerance_%: 5; VDC_V: 50; Value2: 50V; TaMin_C: -55; TaMax_C: 125; Cap_Case: 0603; SizeArea_mm2: 1.28; SizeAreaWB_mm2: 4.68; SizeX_mm: 1.6; SizeY_mm: 0.8; SizeZ_mm: 1; AEC Category: Q200; AEC Qualified: Y
signal-integrity model Cap
simulation model Cap
footprint 0603
footprint 0603M
footprint 0603L
footprint 0603_HV
footprint 0603S
pins: 1, 2

## CGA3E2NP01H100D080AA
designator C?  ValueDisplayed: 10pF  (hidden comment: CGA3E2NP01H100D080AA)
CAP, CERM, 10 pF, 50 V,+/- 5%, C0G/NP0, 0603; Manufacturer: TDK; Polarized: N; CompType: Capacitor; Value: 10pF; U/M: EA; Cap_F: 0.00000000001; Tolerance_%: 5; VDC_V: 50; Value2: 50V; TaMin_C: -55; TaMax_C: 150; Cap_Case: 0603; SizeArea_mm2: 1.28; SizeAreaWB_mm2: 4.68; SizeX_mm: 1.6; SizeY_mm: 0.8; SizeZ_mm: 1; AEC Category: Q200
signal-integrity model Cap
simulation model Cap
footprint 0603
footprint 0603M
footprint 0603L
footprint 0603_HV
footprint 0603S
pins: 1, 2

## CGA3E2NP01H101J080AA
designator C?  ValueDisplayed: 100pF  (hidden comment: CGA3E2NP01H101J080AA)
CAP, CERM, 100 pF, 50 V,+/- 5%, C0G/NP0, AEC-Q200 Grade 0, 0603; Manufacturer: TDK; Polarized: N; CompType: Capacitor; Value: 100pF; U/M: EA; Cap_F: 0.0000000001; Tolerance_%: 5; VDC_V: 50; Value2: 50V; TaMin_C: -55; TaMax_C: 150; Cap_Case: 0603; SizeArea_mm2: 1.28; SizeAreaWB_mm2: 4.68; SizeX_mm: 1.6; SizeY_mm: 0.8; SizeZ_mm: 1; AEC Category: Q200; AEC Qualified: Y; AEC Grade: 0; Green_Lifecycle: Active; Green_REACh: Passed
signal-integrity model Cap
simulation model Cap
footprint 0603
footprint 0603M
footprint 0603L
footprint 0603_HV
footprint 0603S
pins: 1, 2

## CGA3E2NP01H330J080AA
designator C?  ValueDisplayed: 33pF  (hidden comment: CGA3E2NP01H330J080AA)
CAP, CERM, 33 pF, 50 V,+/- 5%, C0G/NP0, AEC-Q200 Grade 0, 0603; Manufacturer: TDK; Polarized: N; CompType: Capacitor; Value: 33pF; U/M: EA; Cap_F: 0.000000000033; Tolerance_%: 5; VDC_V: 50; Value2: 50V; TaMin_C: -55; TaMax_C: 150; Cap_Case: 0603; SizeArea_mm2: 1.28; SizeAreaWB_mm2: 4.68; SizeX_mm: 1.6; SizeY_mm: 0.8; SizeZ_mm: 1; AEC Category: Q200; AEC Qualified: Y; AEC Grade: 0; Green_Lifecycle: Active; Green_REACh: Passed
signal-integrity model Cap
simulation model Cap
footprint 0603
footprint 0603M
footprint 0603L
footprint 0603_HV
footprint 0603S
pins: 1, 2

## CGA3E2X7R1E104K080AA
designator C?  ValueDisplayed: 0.1µF  (hidden comment: CGA3E2X7R1E104K080AA)
CAP, CERM, 0.1 µF, 25 V,+/- 10%, X7R, AEC-Q200 Grade 1, 0603; Manufacturer: TDK; Polarized: N; CompType: Capacitor; Value: 0.1uF; U/M: EA; Cap_F: 0.0000001; Tolerance_%: 10; VDC_V: 25; Value2: 25V; TaMin_C: -55; TaMax_C: 125; Cap_Case: 0603; SizeArea_mm2: 1.28; SizeAreaWB_mm2: 4.68; SizeX_mm: 1.6; SizeY_mm: 0.8; SizeZ_mm: 1; AEC Category: Q200; AEC Qualified: Y
signal-integrity model Cap
simulation model Cap
footprint 0603
footprint 0603M
footprint 0603L
footprint 0603_HV
footprint 0603S
pins: 1, 2

## CGA3E2X7R1H104K080AA
designator C?  ValueDisplayed: 0.1µF  (hidden comment: CGA3E2X7R1H104K080AA)
CAP, CERM, 0.1 µF, 50 V,+/- 10%, X7R, AEC-Q200 Grade 1, 0603; Manufacturer: TDK; Polarized: N; CompType: Capacitor; Value: 0.1uF; U/M: EA; Cap_F: 0.0000001; Tolerance_%: 10; ESR_ohm: 0.0296; Value1: 0.0296 ohm; VDC_V: 50; Value2: 50V; IRMS_A: 0.97199; TaMin_C: -55; TaMax_C: 125; Cap_Case: 0603; SizeArea_mm2: 1.28; SizeAreaWB_mm2: 4.68; SizeX_mm: 1.6; SizeY_mm: 0.8; SizeZ_mm: 1; AEC Category: Q200; AEC Qualified: Y; Green_Lifecycle: Active; Green_REACh: Passed
signal-integrity model Cap
simulation model Cap
footprint 0603
footprint 0603M
footprint 0603L
footprint 0603_HV
footprint 0603S
pins: 1, 2

## CGA3E2X7R1H473K080AA
designator C?  ValueDisplayed: 0.047µF  (hidden comment: CGA3E2X7R1H473K080AA)
CAP, CERM, 0.047 µF, 50 V,+/- 10%, X7R, AEC-Q200 Grade 1, 0603; Manufacturer: TDK; Polarized: N; CompType: Capacitor; Value: 0.047uF; U/M: EA; Cap_F: 0.000000047; Tolerance_%: 10; ESR_ohm: 0.049007; Value1: 0.049007 ohm; VDC_V: 50; Value2: 50V; IRMS_A: 0.767528; TaMin_C: -55; TaMax_C: 125; Cap_Case: 0603; SizeArea_mm2: 1.28; SizeAreaWB_mm2: 4.68; SizeX_mm: 1.6; SizeY_mm: 0.8; SizeZ_mm: 1; AEC Category: Q200; AEC Qualified: Y
signal-integrity model Cap
simulation model Cap
footprint 0603
footprint 0603M
footprint 0603L
footprint 0603_HV
footprint 0603S
pins: 1, 2

## CGA3E2X7R1H683K080AA
designator C?  ValueDisplayed: 0.068µF  (hidden comment: CGA3E2X7R1H683K080AA)
CAP, CERM, 0.068 µF, 50 V,+/- 10%, X7R, AEC-Q200 Grade 1, 0603; Manufacturer: TDK; Polarized: N; CompType: Capacitor; Value: 0.068uF; U/M: EA; Cap_F: 0.000000068; Tolerance_%: 10; ESR_ohm: 0.035979; Value1: 0.035979 ohm; VDC_V: 50; Value2: 50V; IRMS_A: 0.886483; TaMin_C: -55; TaMax_C: 125; Cap_Case: 0603; SizeArea_mm2: 1.28; SizeAreaWB_mm2: 4.68; SizeX_mm: 1.6; SizeY_mm: 0.8; SizeZ_mm: 1; AEC Category: Q200; AEC Qualified: Y
signal-integrity model Cap
simulation model Cap
footprint 0603
footprint 0603M
footprint 0603L
footprint 0603_HV
footprint 0603S
pins: 1, 2

## CGA3E2X7R2A102K080AA
designator C?  ValueDisplayed: 1000pF  (hidden comment: CGA3E2X7R2A102K080AA)
CAP, CERM, 1000 pF, 100 V,+/- 10%, X7R, AEC-Q200 Grade 1, 0603; Manufacturer: TDK; Polarized: N; CompType: Capacitor; Value: 1000pF; U/M: EA; Cap_F: 0.000000001; Tolerance_%: 10; ESR_ohm: 1.97137; Value1: 1.97137 ohm; VDC_V: 100; Value2: 100V; IRMS_A: 0.305705; TaMin_C: -55; TaMax_C: 125; Cap_Case: 0603; SizeArea_mm2: 1.28; SizeAreaWB_mm2: 4.68; SizeX_mm: 1.6; SizeY_mm: 0.8; SizeZ_mm: 1; AEC Category: Q200; AEC Qualified: Y; Green_Lifecycle: Active; Green_REACh: Passed
signal-integrity model Cap
simulation model Cap
footprint 0603
footprint 0603M
footprint 0603L
footprint 0603_HV
footprint 0603S
pins: 1, 2

## CGA3E2X7R2A103K080AA
designator C?  ValueDisplayed: 0.01µF  (hidden comment: CGA3E2X7R2A103K080AA)
CAP, CERM, 0.01 µF, 100 V,+/- 10%, X7R, AEC-Q200 Grade 1, 0603; Manufacturer: TDK; Polarized: N; CompType: Capacitor; Value: 0.01uF; U/M: EA; Cap_F: 0.00000001; Tolerance_%: 10; ESR_ohm: 0.235428; Value1: 0.235428 ohm; VDC_V: 100; Value2: 100V; IRMS_A: 0.396995; TaMin_C: -55; TaMax_C: 125; Cap_Case: 0603; SizeArea_mm2: 1.28; SizeAreaWB_mm2: 4.68; SizeX_mm: 1.6; SizeY_mm: 0.8; SizeZ_mm: 1; AEC Category: Q200; AEC Qualified: Y
signal-integrity model Cap
simulation model Cap
footprint 0603
footprint 0603M
footprint 0603L
footprint 0603_HV
footprint 0603S
pins: 1, 2

## CGA3E2X7R2A152K080AA
designator C?  ValueDisplayed: 1500pF  (hidden comment: CGA3E2X7R2A152K080AA)
CAP, CERM, 1500 pF, 100 V,+/- 10%, X7R, AEC-Q200 Grade 1, 0603; Manufacturer: TDK; Polarized: N; CompType: Capacitor; Value: 1500pF; U/M: EA; Cap_F: 0.0000000015; Tolerance_%: 10; ESR_ohm: 1.35428; Value1: 1.35428 ohm; VDC_V: 100; Value2: 100V; IRMS_A: 0.28963; TaMin_C: -55; TaMax_C: 125; Cap_Case: 0603; SizeArea_mm2: 1.28; SizeAreaWB_mm2: 4.68; SizeX_mm: 1.6; SizeY_mm: 0.8; SizeZ_mm: 1; AEC Category: Q200; AEC Qualified: Y
signal-integrity model Cap
simulation model Cap
footprint 0603
footprint 0603M
footprint 0603L
footprint 0603_HV
footprint 0603S
pins: 1, 2

## CGA3E2X7R2A153K080AA
designator C?  ValueDisplayed: 0.015µF  (hidden comment: CGA3E2X7R2A153K080AA)
CAP, CERM, 0.015 µF, 100 V,+/- 10%, X7R, AEC-Q200 Grade 1, 0603; Manufacturer: TDK; Polarized: N; CompType: Capacitor; Value: 0.015uF; U/M: EA; Cap_F: 0.000000015; Tolerance_%: 10; ESR_ohm: 0.128703; Value1: 0.128703 ohm; VDC_V: 100; Value2: 100V; IRMS_A: 0.506826; TaMin_C: -55; TaMax_C: 125; Cap_Case: 0603; SizeArea_mm2: 1.28; SizeAreaWB_mm2: 4.68; SizeX_mm: 1.6; SizeY_mm: 0.8; SizeZ_mm: 1; AEC Category: Q200; AEC Qualified: Y
signal-integrity model Cap
simulation model Cap
footprint 0603
footprint 0603M
footprint 0603L
footprint 0603_HV
footprint 0603S
pins: 1, 2

## CGA3E2X7R2A222K080AA
designator C?  ValueDisplayed: 2200pF  (hidden comment: CGA3E2X7R2A222K080AA)
CAP, CERM, 2200 pF, 100 V,+/- 10%, X7R, AEC-Q200 Grade 1, 0603; Manufacturer: TDK; Polarized: N; CompType: Capacitor; Value: 2200pF; U/M: EA; Cap_F: 0.0000000022; Tolerance_%: 10; ESR_ohm: 0.923948; Value1: 0.923948 ohm; VDC_V: 100; Value2: 100V; IRMS_A: 0.295638; TaMin_C: -55; TaMax_C: 125; Cap_Case: 0603; SizeArea_mm2: 1.28; SizeAreaWB_mm2: 4.68; SizeX_mm: 1.6; SizeY_mm: 0.8; SizeZ_mm: 1; AEC Category: Q200; AEC Qualified: Y
signal-integrity model Cap
simulation model Cap
footprint 0603
footprint 0603M
footprint 0603L
footprint 0603_HV
footprint 0603S
pins: 1, 2

## CGA3E2X7R2A223K080AA
designator C?  ValueDisplayed: 0.022µF  (hidden comment: CGA3E2X7R2A223K080AA)
CAP, CERM, 0.022 µF, 100 V,+/- 10%, X7R, AEC-Q200 Grade 1, 0603; Manufacturer: TDK; Polarized: N; CompType: Capacitor; Value: 0.022uF; U/M: EA; Cap_F: 0.000000022; Tolerance_%: 10; ESR_ohm: 0.083542; Value1: 0.083542 ohm; VDC_V: 100; Value2: 100V; IRMS_A: 0.609312; TaMin_C: -55; TaMax_C: 125; Cap_Case: 0603; SizeArea_mm2: 1.28; SizeAreaWB_mm2: 4.68; SizeX_mm: 1.6; SizeY_mm: 0.8; SizeZ_mm: 1; AEC Category: Q200; AEC Qualified: Y
signal-integrity model Cap
simulation model Cap
footprint 0603
footprint 0603M
footprint 0603L
footprint 0603_HV
footprint 0603S
pins: 1, 2

## CGA3E2X7R2A332K080AA
designator C?  ValueDisplayed: 3300pF  (hidden comment: CGA3E2X7R2A332K080AA)
CAP, CERM, 3300 pF, 100 V,+/- 10%, X7R, AEC-Q200 Grade 1, 0603; Manufacturer: TDK; Polarized: N; CompType: Capacitor; Value: 3300pF; U/M: EA; Cap_F: 0.0000000033; Tolerance_%: 10; ESR_ohm: 0.662155; Value1: 0.662155 ohm; VDC_V: 100; Value2: 100V; IRMS_A: 0.30254; TaMin_C: -55; TaMax_C: 125; Cap_Case: 0603; SizeArea_mm2: 1.28; SizeAreaWB_mm2: 4.68; SizeX_mm: 1.6; SizeY_mm: 0.8; SizeZ_mm: 1; AEC Category: Q200; AEC Qualified: Y
signal-integrity model Cap
simulation model Cap
footprint 0603
footprint 0603M
footprint 0603L
footprint 0603_HV
footprint 0603S
pins: 1, 2

## CGA3E2X7R2A472K080AA
designator C?  ValueDisplayed: 4700pF  (hidden comment: CGA3E2X7R2A472K080AA)
CAP, CERM, 4700 pF, 100 V,+/- 10%, X7R, AEC-Q200 Grade 1, 0603; Manufacturer: TDK; Polarized: N; CompType: Capacitor; Value: 4700pF; U/M: EA; Cap_F: 0.0000000047; Tolerance_%: 10; ESR_ohm: 0.469862; Value1: 0.469862 ohm; VDC_V: 100; Value2: 100V; IRMS_A: 0.32335; TaMin_C: -55; TaMax_C: 125; Cap_Case: 0603; SizeArea_mm2: 1.28; SizeAreaWB_mm2: 4.68; SizeX_mm: 1.6; SizeY_mm: 0.8; SizeZ_mm: 1; AEC Category: Q200; AEC Qualified: Y
signal-integrity model Cap
simulation model Cap
footprint 0603
footprint 0603M
footprint 0603L
footprint 0603_HV
footprint 0603S
pins: 1, 2

## CGA3E2X7R2A682K080AA
designator C?  ValueDisplayed: 6800pF  (hidden comment: CGA3E2X7R2A682K080AA)
CAP, CERM, 6800 pF, 100 V,+/- 10%, X7R, AEC-Q200 Grade 1, 0603; Manufacturer: TDK; Polarized: N; CompType: Capacitor; Value: 6800pF; U/M: EA; Cap_F: 0.0000000068; Tolerance_%: 10; ESR_ohm: 0.35202; Value1: 0.35202 ohm; VDC_V: 100; Value2: 100V; IRMS_A: 0.34558; TaMin_C: -55; TaMax_C: 125; Cap_Case: 0603; SizeArea_mm2: 1.28; SizeAreaWB_mm2: 4.68; SizeX_mm: 1.6; SizeY_mm: 0.8; SizeZ_mm: 1; AEC Category: Q200; AEC Qualified: Y
signal-integrity model Cap
simulation model Cap
footprint 0603
footprint 0603M
footprint 0603L
footprint 0603_HV
footprint 0603S
pins: 1, 2

## CGA3E2X8R1E104K080AA
designator C?  ValueDisplayed: 0.1µF  (hidden comment: CGA3E2X8R1E104K080AA)
CAP, CERM, 0.1 µF, 25 V,+/- 10%, X8R, AEC-Q200 Grade 0, 0603; Manufacturer: TDK; Polarized: N; CompType: Capacitor; Value: 0.1uF; U/M: EA; Cap_F: 0.0000001; Tolerance_%: 10; VDC_V: 25; Value2: 25V; TaMin_C: -55; TaMax_C: 150; Cap_Case: 0603; SizeArea_mm2: 1.28; SizeAreaWB_mm2: 4.68; SizeX_mm: 1.6; SizeY_mm: 0.8; SizeZ_mm: 1; AEC Category: Q200; AEC Qualified: Y; AEC Grade: 0; Green_Lifecycle: Active; Green_REACh: Passed
signal-integrity model Cap
simulation model Cap
footprint 0603
footprint 0603M
footprint 0603L
footprint 0603_HV
footprint 0603S
pins: 1, 2

## CGA3E3X5R1A225K080AB
designator C?  ValueDisplayed: 2.2µF  (hidden comment: CGA3E3X5R1A225K080AB)
CAP, CERM, 2.2 µF, 10 V,+/- 10%, X5R, AEC-Q200 Grade 3, 0603; Manufacturer: TDK; Polarized: N; CompType: Capacitor; Value: 2.2uF; U/M: EA; Cap_F: 0.0000022; Tolerance_%: 10; Value2: 10V; TaMin_C: -55; TaMax_C: 85; Cap_Case: 0603; SizeArea_mm2: 1.28; SizeAreaWB_mm2: 4.68; SizeX_mm: 1.6; SizeY_mm: 0.8; SizeZ_mm: 1; AEC Category: Q200; AEC Qualified: Y; AEC Grade: 3
signal-integrity model Cap
simulation model Cap
footprint 0603
footprint 0603M
footprint 0603L
footprint 0603_HV
footprint 0603S
pins: 1, 2

## CGA3E3X7R1E474K080AB
designator C?  ValueDisplayed: 0.47µF  (hidden comment: CGA3E3X7R1E474K080AB)
CAP, CERM, 0.47 µF, 25 V,+/- 10%, X7R, AEC-Q200 Grade 1, 0603; Manufacturer: TDK; Polarized: N; CompType: Capacitor; Value: 0.47uF; U/M: EA; Cap_F: 0.00000047; Tolerance_%: 10; VDC_V: 25; Value2: 25V; TaMin_C: -55; TaMax_C: 125; Cap_Case: 0603; SizeArea_mm2: 1.28; SizeAreaWB_mm2: 4.68; SizeX_mm: 1.6; SizeY_mm: 0.8; SizeZ_mm: 1; AEC Category: Q200; AEC Qualified: Y
signal-integrity model Cap
simulation model Cap
footprint 0603
footprint 0603M
footprint 0603L
footprint 0603_HV
footprint 0603S
pins: 1, 2

## CGA3E3X7R1H154K080AB
designator C?  ValueDisplayed: 0.15µF  (hidden comment: CGA3E3X7R1H154K080AB)
CAP, CERM, 0.15 µF, 50 V,+/- 10%, X7R, AEC-Q200 Grade 1, 0603; Manufacturer: TDK; Polarized: N; CompType: Capacitor; Value: 0.15uF; U/M: EA; Cap_F: 0.00000015; Tolerance_%: 10; ESR_ohm: 0.028863; Value1: 0.028863 ohm; VDC_V: 50; Value2: 50V; IRMS_A: 0.978809; TaMin_C: -55; TaMax_C: 125; Cap_Case: 0603; SizeArea_mm2: 1.28; SizeAreaWB_mm2: 4.68; SizeX_mm: 1.6; SizeY_mm: 0.8; SizeZ_mm: 1; AEC Category: Q200; AEC Qualified: Y
signal-integrity model Cap
simulation model Cap
footprint 0603
footprint 0603M
footprint 0603L
footprint 0603_HV
footprint 0603S
pins: 1, 2

## CGA3E3X7R1H224K080AB
designator C?  ValueDisplayed: 0.22µF  (hidden comment: CGA3E3X7R1H224K080AB)
CAP, CERM, 0.22 µF, 50 V,+/- 10%, X7R, AEC-Q200 Grade 1, 0603; Manufacturer: TDK; Polarized: N; CompType: Capacitor; Value: 0.22uF; U/M: EA; Cap_F: 0.00000022; Tolerance_%: 10; ESR_ohm: 0.021699; Value1: 0.021699 ohm; VDC_V: 50; Value2: 50V; IRMS_A: 1.12496; TaMin_C: -55; TaMax_C: 125; Cap_Case: 0603; SizeArea_mm2: 1.28; SizeAreaWB_mm2: 4.68; SizeX_mm: 1.6; SizeY_mm: 0.8; SizeZ_mm: 1; AEC Category: Q200; AEC Qualified: Y
signal-integrity model Cap
simulation model Cap
footprint 0603
footprint 0603M
footprint 0603L
footprint 0603_HV
footprint 0603S
pins: 1, 2

## CGA3E3X7R1H334K080AB
designator C?  ValueDisplayed: 0.33µF  (hidden comment: CGA3E3X7R1H334K080AB)
CAP, CERM, 0.33 µF, 50 V,+/- 10%, X7R, AEC-Q200 Grade 1, 0603; Manufacturer: TDK; Polarized: N; CompType: Capacitor; Value: 0.33uF; U/M: EA; Cap_F: 0.00000033; Tolerance_%: 10; ESR_ohm: 0.01584; Value1: 0.01584 ohm; VDC_V: 50; Value2: 50V; IRMS_A: 1.31353; TaMin_C: -55; TaMax_C: 125; Cap_Case: 0603; SizeArea_mm2: 1.28; SizeAreaWB_mm2: 4.68; SizeX_mm: 1.6; SizeY_mm: 0.8; SizeZ_mm: 1; AEC Category: Q200; AEC Qualified: Y
signal-integrity model Cap
simulation model Cap
footprint 0603
footprint 0603M
footprint 0603L
footprint 0603_HV
footprint 0603S
pins: 1, 2

## CGA3E3X7R1H474K080AB
designator C?  ValueDisplayed: 0.47µF  (hidden comment: CGA3E3X7R1H474K080AB)
CAP, CERM, 0.47 µF, 50 V,+/- 10%, X7R, AEC-Q200 Grade 1, 0603; Manufacturer: TDK; Polarized: N; CompType: Capacitor; Value: 0.47uF; U/M: EA; Cap_F: 0.00000047; Tolerance_%: 10; ESR_ohm: 0.01064; Value1: 0.01064 ohm; VDC_V: 50; Value2: 50V; IRMS_A: 1.59966; TaMin_C: -55; TaMax_C: 125; Cap_Case: 0603; SizeArea_mm2: 1.28; SizeAreaWB_mm2: 4.68; SizeX_mm: 1.6; SizeY_mm: 0.8; SizeZ_mm: 1; AEC Category: Q200; AEC Qualified: Y
signal-integrity model Cap
simulation model Cap
footprint 0603
footprint 0603M
footprint 0603L
footprint 0603_HV
footprint 0603S
pins: 1, 2

## CGA3E3X7R1H474K080AE
designator C?  ValueDisplayed: 0.47µF  (hidden comment: CGA3E3X7R1H474K080AE)
CAP, CERM, 0.47 µF, 50 V,+/- 10%, X7R, AEC-Q200 Grade 1, 0603; Manufacturer: TDK; Polarized: N; CompType: Capacitor; Value: 0.47uF; U/M: EA; Cap_F: 0.00000047; Tolerance_%: 10; VDC_V: 50; Value2: 50V; TaMin_C: -55; TaMax_C: 125; Cap_Case: 0603; SizeArea_mm2: 1.28; SizeAreaWB_mm2: 4.68; SizeX_mm: 1.6; SizeY_mm: 0.8; SizeZ_mm: 1; AEC Category: Q200; AEC Qualified: Y
signal-integrity model Cap
simulation model Cap
footprint 0603
footprint 0603M
footprint 0603L
footprint 0603_HV
footprint 0603S
pins: 1, 2

## CGA3E3X7R1H474M080AE
designator C?  ValueDisplayed: 0.47µF  (hidden comment: CGA3E3X7R1H474M080AE)
CAP, CERM, 0.47 µF, 50 V,+/- 20%, X7R, AEC-Q200 Grade 1, 0603; Manufacturer: TDK; Polarized: N; CompType: Capacitor; Value: 0.47uF; U/M: EA; Cap_F: 0.00000047; Tolerance_%: 20; VDC_V: 50; Value2: 50V; TaMin_C: -55; TaMax_C: 125; Cap_Case: 0603; SizeArea_mm2: 1.28; SizeAreaWB_mm2: 4.68; SizeX_mm: 1.6; SizeY_mm: 0.8; SizeZ_mm: 1; AEC Category: Q200; AEC Qualified: Y
signal-integrity model Cap
simulation model Cap
footprint 0603
footprint 0603M
footprint 0603L
footprint 0603_HV
footprint 0603S
pins: 1, 2

## CGA3E3X7S2A104K080AB
designator C?  ValueDisplayed: 0.1µF  (hidden comment: CGA3E3X7S2A104K080AB)
CAP, CERM, 0.1 µF, 100 V,+/- 10%, X7S, AEC-Q200 Grade 1, 0603; Manufacturer: TDK; Polarized: N; CompType: Capacitor; Value: 0.1uF; U/M: EA; Cap_F: 0.0000001; Tolerance_%: 10; ESR_ohm: 0.04959; Value1: 0.04959 ohm; VDC_V: 100; Value2: 100V; IRMS_A: 0.751618; TaMin_C: -55; TaMax_C: 125; Cap_Case: 0603; SizeArea_mm2: 1.28; SizeAreaWB_mm2: 4.68; SizeX_mm: 1.6; SizeY_mm: 0.8; SizeZ_mm: 1; AEC Category: Q200; AEC Qualified: Y
signal-integrity model Cap
simulation model Cap
footprint 0603
footprint 0603M
footprint 0603L
footprint 0603_HV
footprint 0603S
pins: 1, 2

## CGA3E3X7S2A333K080AB
designator C?  ValueDisplayed: 0.033µF  (hidden comment: CGA3E3X7S2A333K080AB)
CAP, CERM, 0.033 µF, 100 V,+/- 10%, X7S, AEC-Q200 Grade 1, 0603; Manufacturer: TDK; Polarized: N; CompType: Capacitor; Value: 0.033uF; U/M: EA; Cap_F: 0.000000033; Tolerance_%: 10; ESR_ohm: 0.139637; Value1: 0.139637 ohm; VDC_V: 100; Value2: 100V; IRMS_A: 0.462257; TaMin_C: -55; TaMax_C: 125; Cap_Case: 0603; SizeArea_mm2: 1.28; SizeAreaWB_mm2: 4.68; SizeX_mm: 1.6; SizeY_mm: 0.8; SizeZ_mm: 1; AEC Category: Q200; AEC Qualified: Y
signal-integrity model Cap
simulation model Cap
footprint 0603
footprint 0603M
footprint 0603L
footprint 0603_HV
footprint 0603S
pins: 1, 2

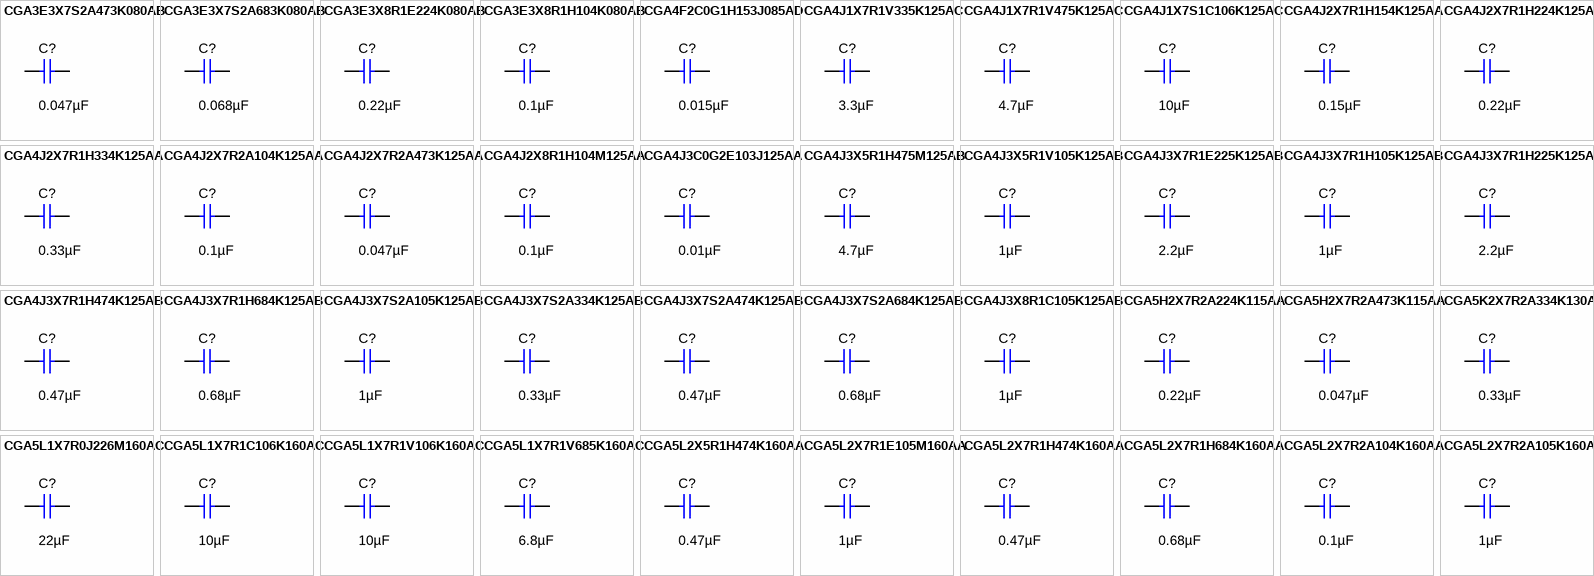
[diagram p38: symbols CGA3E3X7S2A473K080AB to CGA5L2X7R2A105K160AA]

## CGA3E3X7S2A473K080AB
designator C?  ValueDisplayed: 0.047µF  (hidden comment: CGA3E3X7S2A473K080AB)
CAP, CERM, 0.047 µF, 100 V,+/- 10%, X7S, AEC-Q200 Grade 1, 0603; Manufacturer: TDK; Polarized: N; CompType: Capacitor; Value: 0.047uF; U/M: EA; Cap_F: 0.000000047; Tolerance_%: 10; ESR_ohm: 0.089796; Value1: 0.089796 ohm; VDC_V: 100; Value2: 100V; IRMS_A: 0.567484; TaMin_C: -55; TaMax_C: 125; Cap_Case: 0603; SizeArea_mm2: 1.28; SizeAreaWB_mm2: 4.68; SizeX_mm: 1.6; SizeY_mm: 0.8; SizeZ_mm: 1; AEC Category: Q200; AEC Qualified: Y
signal-integrity model Cap
simulation model Cap
footprint 0603
footprint 0603M
footprint 0603L
footprint 0603_HV
footprint 0603S
pins: 1, 2

## CGA3E3X7S2A683K080AB
designator C?  ValueDisplayed: 0.068µF  (hidden comment: CGA3E3X7S2A683K080AB)
CAP, CERM, 0.068 µF, 100 V,+/- 10%, X7S, AEC-Q200 Grade 1, 0603; Manufacturer: TDK; Polarized: N; CompType: Capacitor; Value: 0.068uF; U/M: EA; Cap_F: 0.000000068; Tolerance_%: 10; ESR_ohm: 0.074084; Value1: 0.074084 ohm; VDC_V: 100; Value2: 100V; IRMS_A: 0.61909; TaMin_C: -55; TaMax_C: 125; Cap_Case: 0603; SizeArea_mm2: 1.28; SizeAreaWB_mm2: 4.68; SizeX_mm: 1.6; SizeY_mm: 0.8; SizeZ_mm: 1; AEC Category: Q200; AEC Qualified: Y
signal-integrity model Cap
simulation model Cap
footprint 0603
footprint 0603M
footprint 0603L
footprint 0603_HV
footprint 0603S
pins: 1, 2

## CGA3E3X8R1E224K080AB
designator C?  ValueDisplayed: 0.22µF  (hidden comment: CGA3E3X8R1E224K080AB)
CAP, CERM, 0.22 µF, 25 V,+/- 10%, X8R, AEC-Q200 Grade 0, 0603; Manufacturer: TDK; Polarized: N; CompType: Capacitor; Value: 0.22uF; U/M: EA; Cap_F: 0.00000022; Tolerance_%: 10; VDC_V: 25; Value2: 25V; TaMin_C: -55; TaMax_C: 150; Cap_Case: 0603; SizeArea_mm2: 1.28; SizeAreaWB_mm2: 4.68; SizeX_mm: 1.6; SizeY_mm: 0.8; SizeZ_mm: 1; AEC Category: Q200; AEC Qualified: Y; AEC Grade: 0
signal-integrity model Cap
simulation model Cap
footprint 0603
footprint 0603M
footprint 0603L
footprint 0603_HV
footprint 0603S
pins: 1, 2

## CGA3E3X8R1H104K080AB
designator C?  ValueDisplayed: 0.1µF  (hidden comment: CGA3E3X8R1H104K080AB)
CAP, CERM, 0.1 µF, 50 V,+/- 10%, X8R, AEC-Q200 Grade 0, 0603; Manufacturer: TDK; Polarized: N; CompType: Capacitor; Value: 0.1uF; U/M: EA; Cap_F: 0.0000001; Tolerance_%: 10; VDC_V: 50; Value2: 50V; TaMin_C: -55; TaMax_C: 150; Cap_Case: 0603; SizeArea_mm2: 1.28; SizeAreaWB_mm2: 4.68; SizeX_mm: 1.6; SizeY_mm: 0.8; SizeZ_mm: 1; AEC Category: Q200; AEC Qualified: Y; AEC Grade: 0
signal-integrity model Cap
simulation model Cap
footprint 0603
footprint 0603M
footprint 0603L
footprint 0603_HV
footprint 0603S
pins: 1, 2

## CGA4F2C0G1H153J085AD
designator C?  ValueDisplayed: 0.015µF  (hidden comment: CGA4F2C0G1H153J085AD)
CAP, CERM, 0.015 µF, 50 V,+/- 5%, C0G/NP0, AEC-Q200 Grade 1, 0805; Manufacturer: TDK; Polarized: N; CompType: Capacitor; Value: 0.015uF; U/M: EA; Cap_F: 0.000000015; Tolerance_%: 5; VDC_V: 50; Value2: 50V; TaMin_C: -55; TaMax_C: 125; Cap_Case: 0805; SizeArea_mm2: 2.5; SizeAreaWB_mm2: 6.75; SizeX_mm: 2; SizeY_mm: 1.25; SizeZ_mm: 1.45; AEC Category: Q200; AEC Qualified: Y; AEC Grade: 1
signal-integrity model Cap
simulation model Cap
footprint 0805_HV
footprint 0805_HV1
footprint 0805
footprint 0805M
footprint 0805L
pins: 1, 2

## CGA4J1X7R1V335K125AC
designator C?  ValueDisplayed: 3.3µF  (hidden comment: CGA4J1X7R1V335K125AC)
CAP, CERM, 3.3 µF, 35 V,+/- 10%, X7R, AEC-Q200 Grade 1, 0805; Manufacturer: TDK; Polarized: N; CompType: Capacitor; Value: 3.3uF; U/M: EA; Cap_F: 0.0000033; Tolerance_%: 10; ESR_ohm: 0.002798; Value1: 0.002798 ohm; VDC_V: 35; Value2: 35V; IRMS_A: 3.90156; TaMin_C: -55; TaMax_C: 125; Cap_Case: 0805; SizeArea_mm2: 2.5; SizeAreaWB_mm2: 6.75; SizeX_mm: 2; SizeY_mm: 1.25; SizeZ_mm: 1.45; AEC Category: Q200; AEC Qualified: Y; AEC Grade: 1
signal-integrity model Cap
simulation model Cap
footprint 0805_HV
footprint 0805_HV1
footprint 0805
footprint 0805M
footprint 0805L
pins: 1, 2

## CGA4J1X7R1V475K125AC
designator C?  ValueDisplayed: 4.7µF  (hidden comment: CGA4J1X7R1V475K125AC)
CAP, CERM, 4.7 µF, 35 V,+/- 10%, X7R, AEC-Q200 Grade 1, 0805; Manufacturer: TDK; Polarized: N; CompType: Capacitor; Value: 4.7uF; U/M: EA; Cap_F: 0.0000047; Tolerance_%: 10; ESR_ohm: 0.002346; Value1: 0.002346 ohm; VDC_V: 35; Value2: 35V; IRMS_A: 4.26021; TaMin_C: -55; TaMax_C: 125; Cap_Case: 0805; SizeArea_mm2: 2.5; SizeAreaWB_mm2: 6.75; SizeX_mm: 2; SizeY_mm: 1.25; SizeZ_mm: 1.45; AEC Category: Q200; AEC Qualified: Y; AEC Grade: 1
signal-integrity model Cap
simulation model Cap
footprint 0805_HV
footprint 0805_HV1
footprint 0805
footprint 0805M
footprint 0805L
pins: 1, 2

## CGA4J1X7S1C106K125AC
designator C?  ValueDisplayed: 10µF  (hidden comment: CGA4J1X7S1C106K125AC)
CAP, CERM, 10 µF, 16 V,+/- 10%, X7S, AEC-Q200 Grade 1, 0805; Manufacturer: TDK; Polarized: N; CompType: Capacitor; Value: 10uF; U/M: EA; Cap_F: 0.00001; Tolerance_%: 10; VDC_V: 16; Value2: 16V; TaMin_C: -55; TaMax_C: 125; Cap_Case: 0805; SizeArea_mm2: 2.5; SizeAreaWB_mm2: 6.75; SizeX_mm: 2; SizeY_mm: 1.25; SizeZ_mm: 1.45; AEC Category: Q200; AEC Qualified: Y; AEC Grade: 1
signal-integrity model Cap
simulation model Cap
footprint 0805_HV
footprint 0805_HV1
footprint 0805
footprint 0805M
footprint 0805L
pins: 1, 2

## CGA4J2X7R1H154K125AA
designator C?  ValueDisplayed: 0.15µF  (hidden comment: CGA4J2X7R1H154K125AA)
CAP, CERM, 0.15 µF, 50 V,+/- 10%, X7R, AEC-Q200 Grade 1, 0805; Manufacturer: TDK; Polarized: N; CompType: Capacitor; Value: 0.15uF; U/M: EA; Cap_F: 0.00000015; Tolerance_%: 10; ESR_ohm: 0.019115; Value1: 0.019115 ohm; VDC_V: 50; Value2: 50V; IRMS_A: 1.50852; TaMin_C: -55; TaMax_C: 125; Cap_Case: 0805; SizeArea_mm2: 2.5; SizeAreaWB_mm2: 6.75; SizeX_mm: 2; SizeY_mm: 1.25; SizeZ_mm: 1.45; AEC Category: Q200; AEC Qualified: Y; AEC Grade: 1
signal-integrity model Cap
simulation model Cap
footprint 0805_HV
footprint 0805_HV1
footprint 0805
footprint 0805M
footprint 0805L
pins: 1, 2

## CGA4J2X7R1H224K125AA
designator C?  ValueDisplayed: 0.22µF  (hidden comment: CGA4J2X7R1H224K125AA)
CAP, CERM, 0.22 µF, 50 V,+/- 10%, X7R, AEC-Q200 Grade 1, 0805; Manufacturer: TDK; Polarized: N; CompType: Capacitor; Value: 0.22uF; U/M: EA; Cap_F: 0.00000022; Tolerance_%: 10; ESR_ohm: 0.016949; Value1: 0.016949 ohm; VDC_V: 50; Value2: 50V; IRMS_A: 1.59611; TaMin_C: -55; TaMax_C: 125; Cap_Case: 0805; SizeArea_mm2: 2.5; SizeAreaWB_mm2: 6.75; SizeX_mm: 2; SizeY_mm: 1.25; SizeZ_mm: 1.45; AEC Category: Q200; AEC Qualified: Y; AEC Grade: 1
signal-integrity model Cap
simulation model Cap
footprint 0805_HV
footprint 0805_HV1
footprint 0805
footprint 0805M
footprint 0805L
pins: 1, 2

## CGA4J2X7R1H334K125AA
designator C?  ValueDisplayed: 0.33µF  (hidden comment: CGA4J2X7R1H334K125AA)
CAP, CERM, 0.33 µF, 50 V,+/- 10%, X7R, AEC-Q200 Grade 1, 0805; Manufacturer: TDK; Polarized: N; CompType: Capacitor; Value: 0.33uF; U/M: EA; Cap_F: 0.00000033; Tolerance_%: 10; ESR_ohm: 0.012274; Value1: 0.012274 ohm; VDC_V: 50; Value2: 50V; IRMS_A: 1.87147; TaMin_C: -55; TaMax_C: 125; Cap_Case: 0805; SizeArea_mm2: 2.5; SizeAreaWB_mm2: 6.75; SizeX_mm: 2; SizeY_mm: 1.25; SizeZ_mm: 1.45; AEC Category: Q200; AEC Qualified: Y; AEC Grade: 1
signal-integrity model Cap
simulation model Cap
footprint 0805_HV
footprint 0805_HV1
footprint 0805
footprint 0805M
footprint 0805L
pins: 1, 2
